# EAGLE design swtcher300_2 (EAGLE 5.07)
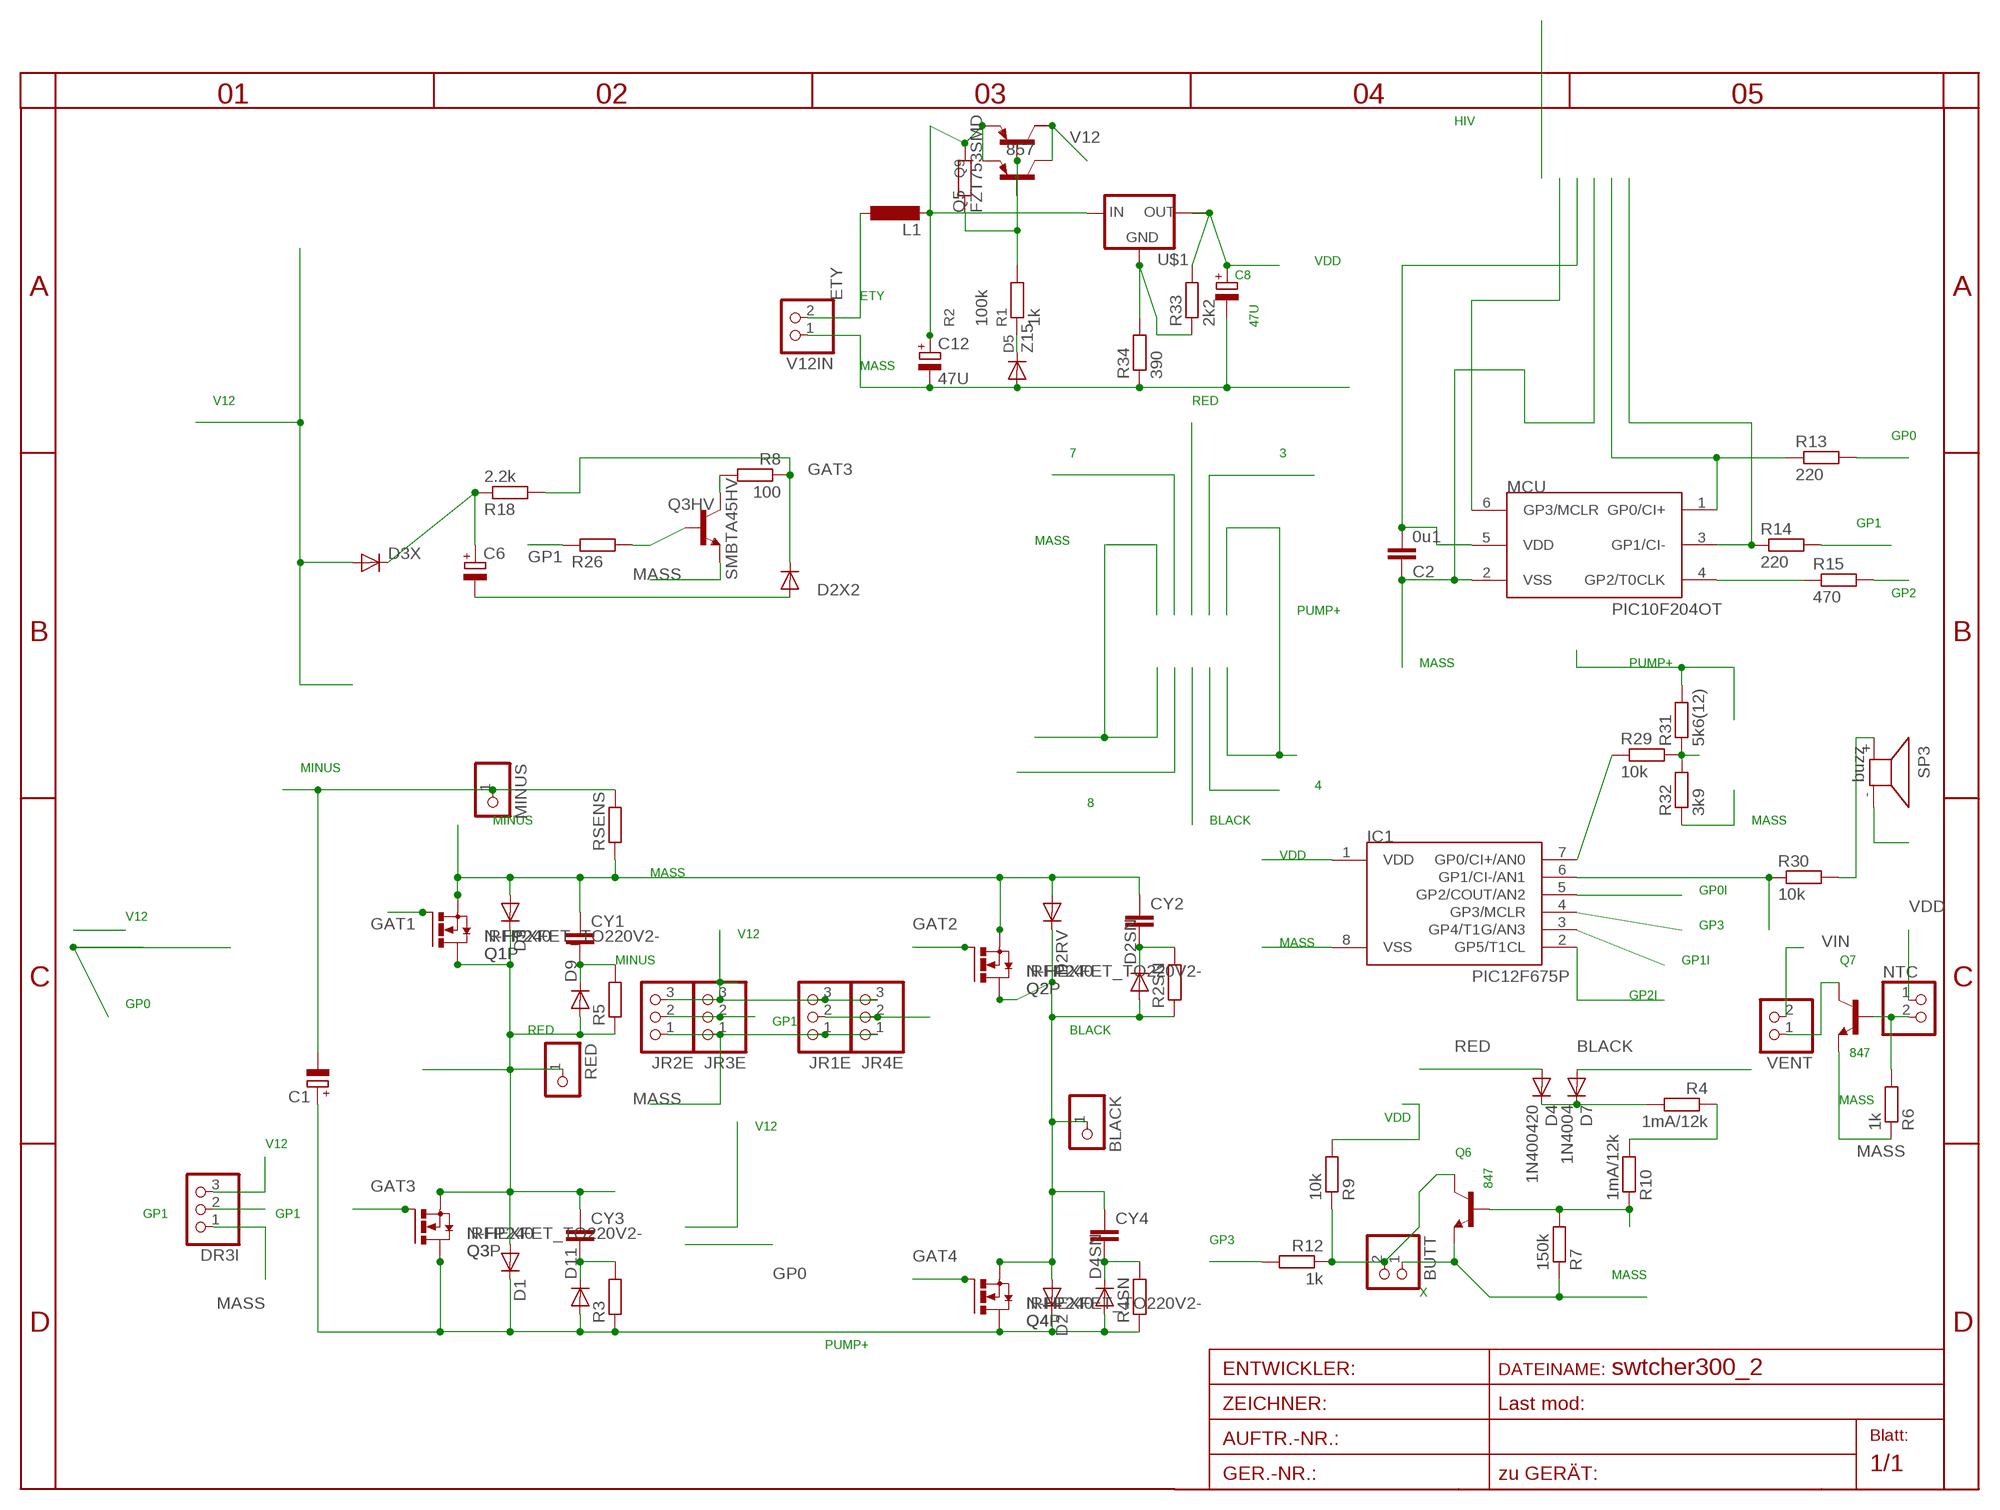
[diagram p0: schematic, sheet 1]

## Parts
BLACK  PINHD-1X14.5MM  [1X4MM5]
BUTT  PINHD-1X2STR  [1X02]
C1  CPOL-EUE5-13  [E5-13]
C2  0u1  C-EUC0805  [C0805]
C6  CPOL-EUC  [PANASONIC_C]
C8  47U  CPOL-EUD  [PANASONIC_D]
C12  47U  CPOL-EUSMCA  [SMC_A]
CY1  CXXC10B6  [XC10B6]
CY2  CXXC10B6  [XC10B6]
CY3  CXXC10B5  [XC10B5]
CY4  CXXC10B6  [XC10B6]
D1  DIODE-SMC  [SMC]
D2  DIODE-SMC  [SMC]
D2RV  DIODE-SMC  [SMC]
D2SN  DIODE-SOD61E  [SOD61E]
D2X2  DIODE-MINIMELF  [MINIMELF]
D3  DIODE-SMC  [SMC]
D3X  DIODE-SMA-DO214  [SMA-DO214AC]
D4  1N400420  [DO41-20]
D4SN  DIODE-SOD61E  [SOD61E]
D5  Z15  DIODE-MINIMELF  [MINIMELF]
D7  1N4004  [D-7.5]
D9  DIODE-SOD61E  [SOD61E]
D11  DIODE-SOD61E  [SOD61E]
DR3I  PINHD-1X3  [1X03]
IC1  PIC12F675P  [DIL8]
JR1E  PINHD-1X3  [1X03]
JR2E  PINHD-1X3  [1X03]
JR3E  PINHD-1X3  [1X03]
JR4E  PINHD-1X3  [1X03]
L1  L-EU0204/5  [0204/5]
MCU  PIC10F204OT  [SOT23-6]
MINUS  PINHD-1X14.5MM  [1X4MM5]
NTC  PINHD-1X2STR  [1X02]
Q1  IRFP240  [TO247BV]
Q1P  N-HEXFET_TO220V2-  [TO220BV2]
Q2  IRFP240  [TO247BV]
Q2P  N-HEXFET_TO220V2-  [TO220BV2]
Q3  IRFP240  [TO247BV]
Q3HV  SMBTA45HV  [SOT23HV]
Q3P  N-HEXFET_TO220V2-  [TO220BV2]
Q4  IRFP240  [TO247BV]
Q4P  N-HEXFET_TO220V2-  [TO220BV2]
Q5  FZT753SMD  [SOT223]
Q6  847  BC847ALT1SMD  [SOT23]
Q7  847  BC847ALT1SMD  [SOT23]
Q9  857  BC857ALT1SMD  [SOT23-BEC]
R1  1k  R-EU_R0805  [R0805]
R2  100k  R-EU_R0805  [R0805]
R2SN  R-EU_0617/22  [0617/22]
R3  R-EU_0617/17  [0617/17]
R4  1mA/12k  R-EU_R1210  [R1210]
R4SN  R-EU_0617/22  [0617/22]
R5  R-EU_0617/22  [0617/22]
R6  1k  R-EU_R0805  [R0805]
R7  150k  R-EU_R0805  [R0805]
R8  100  R-EU_R0805  [R0805]
R9  10k  R-EU_R0805  [R0805]
R10  1mA/12k  R-EU_R1210  [R1210]
R12  1k  R-EU_R0805  [R0805]
R13  220  R-EU_R0805  [R0805]
R14  220  R-EU_R0805  [R0805]
R15  470  R-EU_R0805  [R0805]
R18  2.2k  R-EU_R1206  [R1206]
R26  R-EU_R0805  [R0805]
R29  10k  R-EU_R0805  [R0805]
R30  10k  R-EU_R0805  [R0805]
R31  5k6(12)  R-EU_0207/30  [0207/30]
R32  3k9  R-EU_R0805  [R0805]
R33  2k2  R-EU_R0805  [R0805]
R34  390  R-EU_R0805  [R0805]
RED  PINHD-1X14.5MM  [1X4MM5]
RSENS  R-EU_CERAM35  [CERAM35]
SP3  buzz  KSS12017MM  [KSS1202]
U$1  AP1117  [SOT223]
V12IN  PINHD-1X2STR  [1X02]
VENT  PINHD-1X2STR  [1X02]

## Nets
BLACK: BLACK.1 CY4.1 D2.A D2RV.C D2SN.A D7.A Q2.D Q2P.D Q4.S Q4P.S R2SN.1
ETY: L1.1 V12IN.2
GAT1: Q1.G Q1P.G
GAT2: Q2.G Q2P.G
GAT3: D2X2.C Q3.G Q3P.G R8.1 R18.2
GAT4: Q4.G Q4P.G
GP0: JR1E.2 JR4E.2 R13.2
GP0I: IC1.5(GP2/COUT/AN2) MCU.1(GP0/CI+) R13.1
GP1: DR3I.2 JR2E.2 JR3E.2 R14.2 R26.1
GP1I: IC1.3(GP4/T1G/AN3) MCU.3(GP1/CI-) R14.1
GP2: R15.2
GP2I: IC1.2(GP5/T1CL) MCU.4(GP2/T0CLK) R15.1
GP3: IC1.4(GP3/MCLR) MCU.6(GP3/MCLR) R12.2
MASS: BUTT.1 C2.1 C8.- C12.- CY1.1 CY2.1 D2RV.A D3.A D5.A DR3I.1 IC1.8(VSS) JR1E.1 JR2E.1 JR3E.1 JR4E.1 MCU.2(VSS) Q1.S Q1P.S Q2.S Q2P.S Q3HV.2(E) Q6.2(E) Q7.2(E) R6.1 R7.1 R32.1 R34.1 RSENS.1 SP3.- V12IN.1
MINUS: C1.- MINUS.1 RSENS.2
N$1: D4.C D7.C R4.2
N$2: Q5.1(B) Q9.B R1.2 R2.1
N$3: D5.C R1.1
N$4: Q3HV.3(C) R8.2
N$5: Q6.1(B) R7.2 R10.1
N$7: R4.1 R10.2
N$9: NTC.2 Q7.1(B) R6.2
N$10: Q7.3(C) VENT.1
N$13: C6.+ D3X.K(C) R18.1
N$22: Q3HV.1(B) R26.2
N$24: R30.2 SP3.+
N$30: R33.1 R34.2 U$1.1(GND)
N$31: IC1.6(GP1/CI-/AN1) R30.1
N$34: R29.2 R31.1 R32.2
N$35: IC1.7(GP0/CI+/AN0) R29.1
PUMP+: C1.+ D1.C D2.C D4SN.A D11.A Q3.D Q3P.D Q4.D Q4P.D R3.1 R4SN.1 R31.2
RED: C6.- CY3.1 D1.A D2X2.A D3.C D4.A D9.A Q1.D Q1P.D Q3.S Q3P.S R5.1 RED.1
SNUB1: CY3.2 D11.C R3.2
SNUB2: CY4.2 D4SN.C R4SN.2
SNUB3: CY2.2 D2SN.C R2SN.2
SNUB4: CY1.2 D9.C R5.2
V12: D3X.A DR3I.3 JR1E.3 JR2E.3 JR3E.3 JR4E.3 Q5.2(C) Q9.C
VDD: C2.2 C8.+ IC1.1(VDD) MCU.5(VDD) NTC.1 R9.2 R33.2 U$1.2(OUT) U$1.4(TAB)
VIN: C12.+ L1.2 Q5.3(E) Q9.E R2.2 U$1.3(IN) VENT.2
X: BUTT.2 Q6.3(C) R9.1 R12.1
Unconnected: Q5.4(C/)

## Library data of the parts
BLACK MINUS RED = pinhead:PINHD-1X1: PIN HEADER
BUTT NTC V12IN VENT = pinhead:PINHD-1X2: PIN HEADER
C1 C6 = rcl:CPOL-EU: POLARIZED CAPACITOR, European symbol
C2 = rcl:C-EU: CAPACITOR, European symbol
C8 C12 = rcl-2:CPOL-EU: POLARIZED CAPACITOR, European symbol
CY1-CY4 = rcl:CX: X CAPACITOR
D1 D2 D2RV D2SN D2X2 D3 D3X D4SN D5 D9 D11 = diode:DIODE-: DIODE
D4 D7 = diode:1N4004: DIODE
DR3I JR1E JR2E JR3E JR4E = pinhead:PINHD-1X3: PIN HEADER
IC1 = microchip-5:PIC12F6*: uPC nW 1k Program Flash memory 2x Timer Comparator 10b A/D converter/ 4xIN
L1 = rcl:L-EU: INDUCTOR, European symbol
MCU = microchip-3:PIC10F2*: uPC nW 0,25/0,5k Program Flash memory Comparator
Q1-Q4 = transistor-power:IRFP240: HEXFET Power MosFet Source: http://www.irf.com/
Q1P Q2P Q3P Q4P = transistor-power:N-HEXFET_?-*: HEXFET® Power MOSFET
Q3HV = transistor-npn:SMBTA45
Q5 = transistor-pnp:FZT753SMD: PNP Transistor
Q6 Q7 = transistor-npn:BC847*: NPN Transistor
Q9 = transistor-pnp:BC857*: PNP Transistror
R1-R3 R13-R15 R29-R34 = rcl-2:R-EU_: RESISTOR, European symbol
R2SN R4 R4SN R5-R10 R12 R18 R26 RSENS = rcl:R-EU_: RESISTOR, European symbol
SP3 = buzzer:KSS1201: SPEAKER
U$1 = v-reg:AP1117

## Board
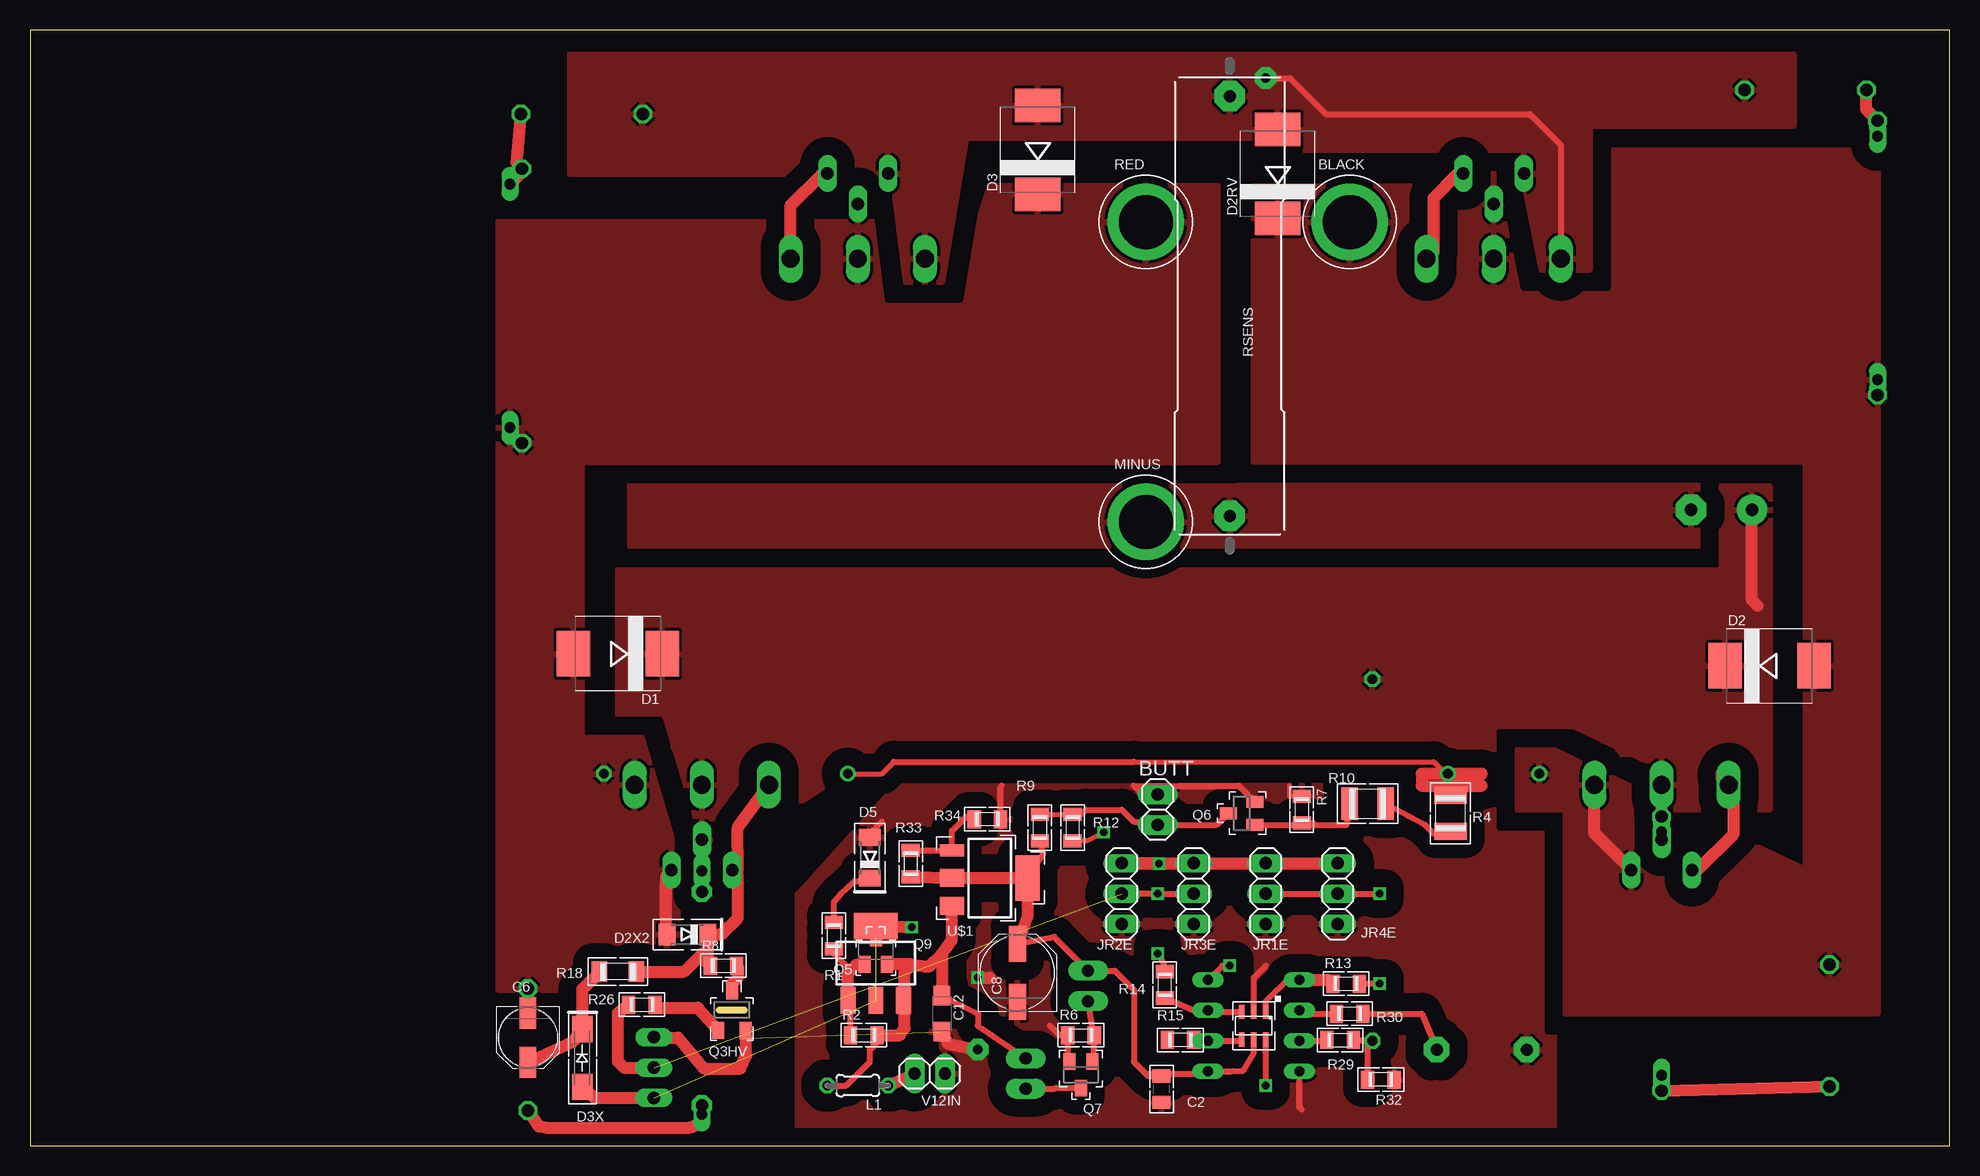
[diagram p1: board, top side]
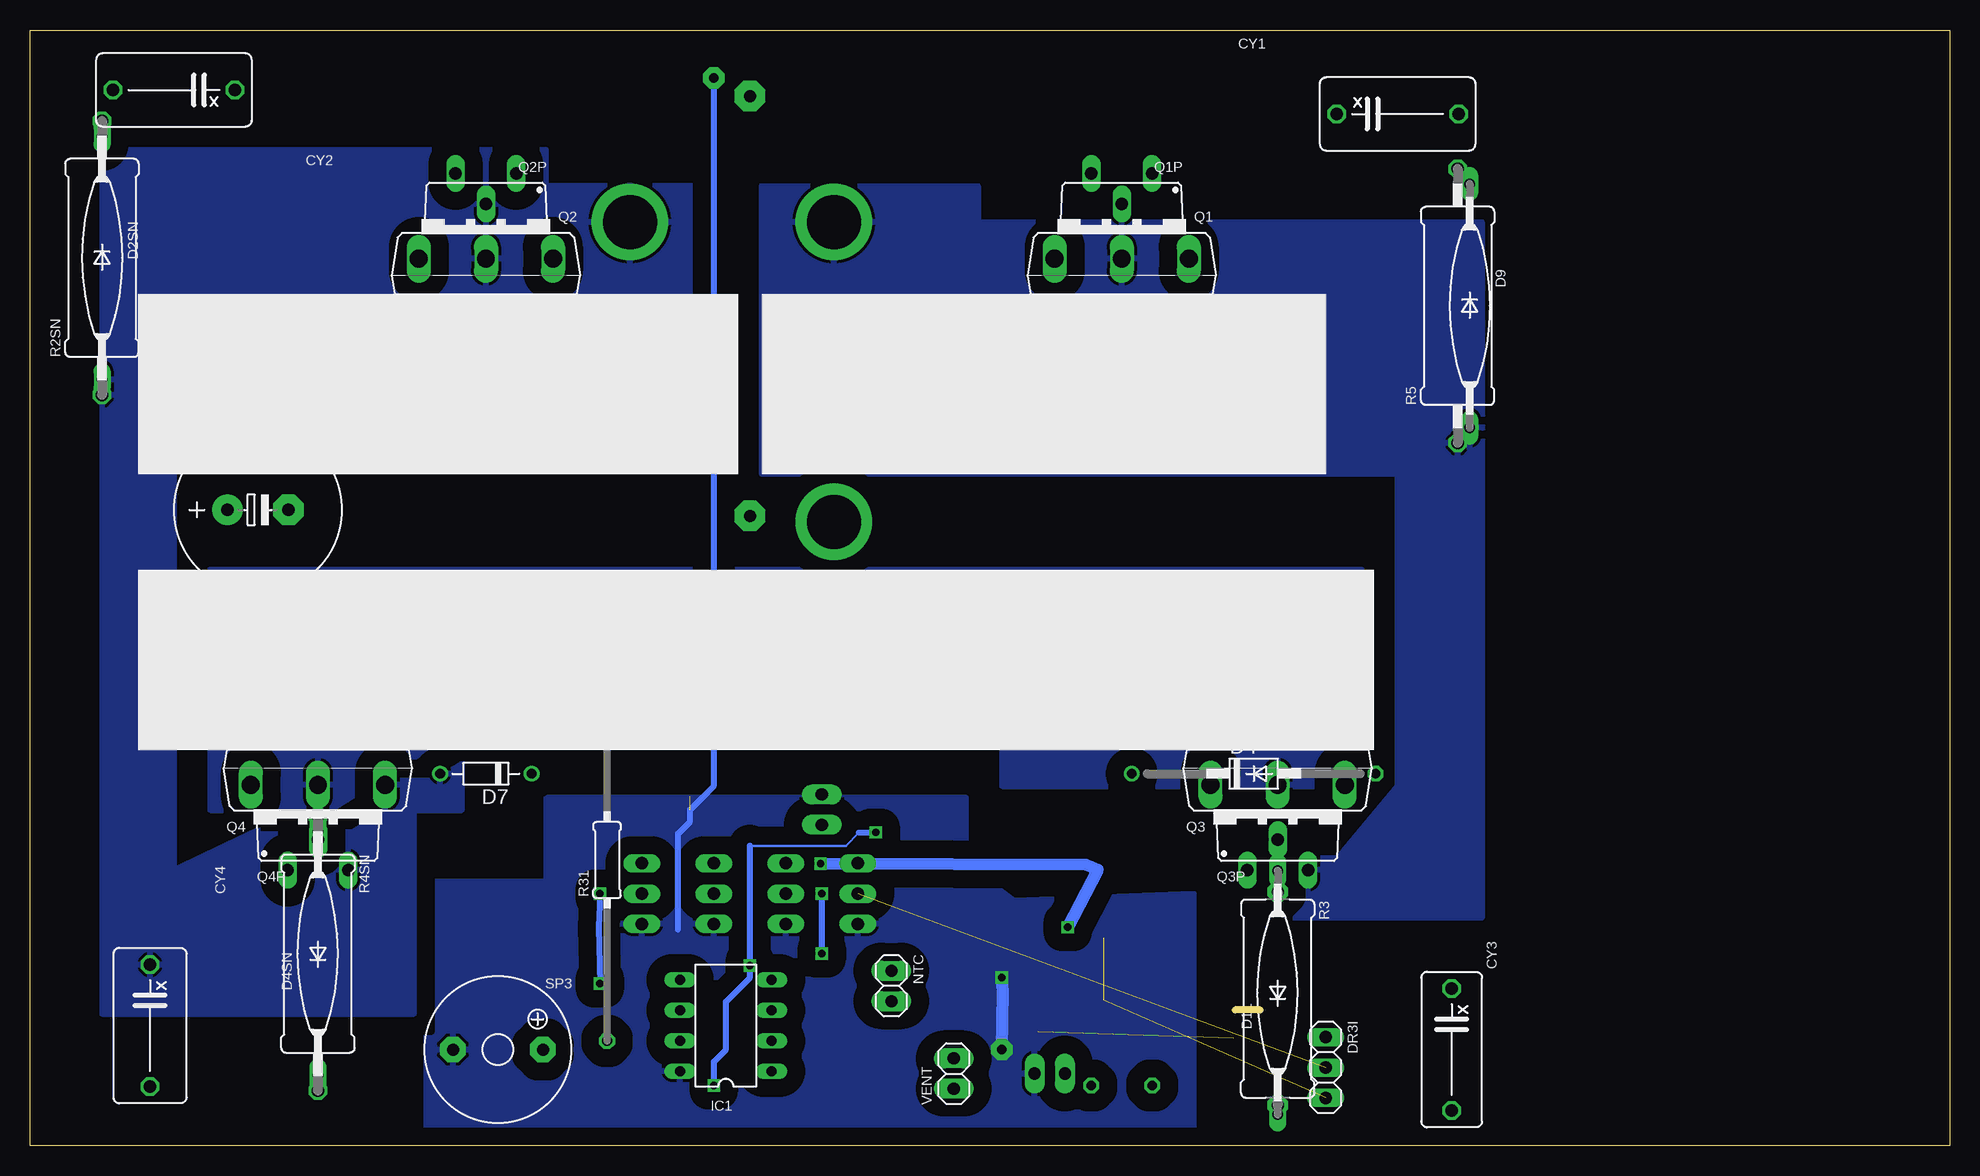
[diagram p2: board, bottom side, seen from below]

Size 160 x 93 mm. Coordinates in mm from the lower left corner, seen from the top.
Outline: 0,0 160,0 160,93 0,93 0,0
Copper layers (1*16): Top 0.035mm / dielectric 1.5mm / Bottom 0.035mm
Design rules "default *": minimum track width 10mil, minimum drill 20mil, track to track 8mil, track to pad 8mil, pad to pad 8mil, via to via 8mil, smd to smd 8mil, copper to edge 40mil, drill to drill 8mil, minimum pad ring 10mil, minimum via ring 8mil, stop-mask expansion 4mil, vias tented up to drill 0mil, thermal gap 10mil

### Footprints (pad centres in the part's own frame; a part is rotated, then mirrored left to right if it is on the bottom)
1X4MM5 = drill 4.5 pad 6.35 round: 1 0,0
1X02 = drill 1.016 pad 1.676 long: 1 -1.27,0; 2 1.27,0
E5-13 = drill 1.016 pad 2.54 round: + -2.54,0 | drill 1.016 pad 2.54 octagon: - 2.54,0
C0805 = smd 1.1 x 1.5: 1 -1.1,0; 2 1.1,0
PANASONIC_C = smd 2.6 x 1.4: + 2.05,0; - -2.05,0
PANASONIC_D = smd 3 x 1.4: + 2.4,0; - -2.4,0
SMC_A = smd 1.6 x 1.4: + -1.5,0; - 1.5,0
XC10B6 = drill 1.016 octagon: 1 -5.08,0; 2 5.08,0
XC10B5 = drill 1.016 octagon: 1 -5.08,0; 2 5.08,0
SMC = smd 2.8 x 3.8: A 3.7,0; C -3.7,0
SOD61E = drill 0.914 long: A 10.16,0; C -10.16,0
MINIMELF = smd 1.4 x 1.8: A 1.7,0; C -1.7,0
SMA-DO214AC = smd 2.2 x 1.7: A 2.4,0; K -2.4,0
DO41-20 = drill 0.8 octagon: A 10.16,0 | drill 0.8 round: C -10.16,0
D-7.5 = drill 0.8 round: A 3.81,0; C -3.81,0
1X03 = drill 1.016 long: 1 -2.54,0; 2 0,0; 3 2.54,0
DIL8 = drill 0.8 long: 1 -3.81,-3.81; 2 -1.27,-3.81; 3 1.27,-3.81; 4 3.81,-3.81; 5 3.81,3.81; 6 1.27,3.81; 7 -1.27,3.81; 8 -3.81,3.81
0204/5 = drill 0.813 octagon: 1 -2.54,0; 2 2.54,0
SOT23-6 = smd 0.45 x 1.2: 1 -1.016,-1.15; 2 0,-1.15; 3 1.016,-1.15; 4 1.016,1.15; 5 0,1.15; 6 -1.016,1.15
TO247BV = drill 1.499 long: D 0,-2.921; G -5.588,-2.921; S 5.588,-2.921
TO220BV2 = drill 1.016 long: D 0,0; G -2.54,-2.54; S 2.54,-2.54
SOT23HV = smd 1 x 1.4: 1 -1.15,-1.7; 2 1.15,-1.7; 3 0,1.6
SOT223 = smd 1.219 x 2.235: 1 -2.311,-3.099; 2 0,-3.099; 3 2.311,-3.099 | smd 3.6 x 2.2: 4 0,3.099
SOT23 = smd 1 x 1.4: 1 -0.95,-1.1; 2 0.95,-1.1; 3 0,1.1
SOT23-BEC = smd 1 x 1.4: B -0.95,-1.1; C 0,1.1; E 0.95,-1.1
R0805 = smd 1.1 x 1.5: 1 -1.1,0; 2 1.1,0
0617/22 = drill 1.016 octagon: 1 -11.43,0; 2 11.43,0
0617/17 = drill 1 pad 1.676 octagon: 1 -8.89,0; 2 8.89,0
R1210 = smd 1.4 x 2.7: 1 -1.5,0; 2 1.5,0
R1206 = smd 1.3 x 1.7: 1 -1.55,0; 2 1.55,0
0207/30 = drill 0.813 octagon: 1 -15.08,0; 2 15.08,0
CERAM35 = drill 1 pad 2.54 octagon: 1 -17.5,0; 2 17.5,0
KSS1202 = drill 1 pad 2.159 octagon: + 3.75,0; - -3.75,0
SOT223' = smd 1 x 2: 1 -2.3,-3.15 | smd 1.5 x 2: 2 0,-3.15; 3 2.3,-3.15 | smd 3.8 x 2: 4 0,3.15

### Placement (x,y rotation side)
BLACK  110,77 0 top
BUTT  94,28 270 top
C1  141,53 0 bottom
C2  94.32,4.7 90 top
C6  41.5,9 270 top
C8  82.3,14.4 90 top
C12  76,11 270 top
CY1  46,86 0 bottom
CY2  148,88 180 bottom
CY3  41.5,8 270 bottom
CY4  150,10 270 bottom
D1  49,41 180 top
D2  145,40 0 top
D2RV  104,81 90 top
D2SN  154,74 270 bottom
D2X2  54.8,17.6 180 top
D3  84,83 90 top
D3X  46.05,7.3 270 top
D4  58,31 0 bottom
D4SN  136,16 90 bottom
D5  70,24 90 top
D7  122,31 180 bottom
D9  40,70 270 bottom
D11  56,12.75 90 bottom
DR3I  52,6.5 270 bottom
IC1  102,10 90 bottom
JR1E  103,21 90 top
JR2E  91,21 90 top
JR3E  97,21 90 top
JR4E  109,21 90 top
L1  69,5 180 top
MCU  102,10 180 top
MINUS  93,52 0 top
NTC  88.2,13.3 270 bottom
Q1  69,71 180 bottom
Q1P  69,78.5 180 bottom
Q2  122,71 180 bottom
Q2P  122,78.5 180 bottom
Q3  56,33 0 bottom
Q3HV  58.5,11.3 0 top
Q3P  56,25.5 0 bottom
Q4  136,33 0 bottom
Q4P  136,25.5 0 bottom
Q5  70.5,15.2 0 top
Q6  101,27.7 90 top
Q7  87.6,5.9 180 top
Q9  70.5,16.2 0 top
R1  67,17.5 270 top
R2  69.5,9.2 0 top
R2SN  154,74 90 bottom
R3  56,12.25 270 bottom
R4  118.4,27.7 90 top
R4SN  136,16 270 bottom
R5  41,70 90 bottom
R6  87.6,9.2 0 top
R7  106,28 270 top
R8  57.8,15 0 top
R9  84.17,26.5 270 top
R10  111.5,28.5 0 top
R12  86.9,26.5 270 top
R13  109.7,13.5 0 top
R14  94.6,13.4 90 top
R15  95.9,8.8 180 top
R18  49,14.5 0 top
R26  51,11.75 0 top
R29  109.2,8.8 0 top
R30  110,11 0 top
R31  111.9,23.8 90 bottom
R32  112.6,5.5 180 top
R33  73.4,23.5 270 top
R34  79.8,27.2 180 top
RED  93,77 0 top
RSENS  100,70 270 top
SP3  121,8 0 bottom
U$1  AP1117  [SOT223']  80,22.3 270 top
V12IN  75,6 180 top
VENT  83,6 90 bottom

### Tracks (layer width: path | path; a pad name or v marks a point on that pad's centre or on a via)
BLACK
  Top 1: Q4.S 130.41,26.01 Q4P.S
  pour Top (isolate 1.5, rank 2): 102,80 117,80 117,83 154,83 154,11 128,11 128,28 124,28 124,33 127,33 148,23 148,57 102,57
  pour Bottom (isolate 1.5, rank 2): 102,80 117,80 117,83 154,83 154,11 128,11 128,28 124,28 124,33 127,33 148,23 148,57 102,57
ETY
  Top 1: L1.1 V12IN.2
GAT1
  Top 1: Q1.G 63.41,78.41 66,81 66.42,81 Q1P.G
GAT2
  Top 1: Q2P.G 119.04,81.04 117,79 117,74.51 Q2.G
GAT3
  Top 1: Q3.G 58.99,26.49 59,23 58.68,23 Q3P.G 59,22.5 59,19 57.6,17.6 D2X2.C 56.5,15.5 56.35,15.35 | R18.2 54.5,14.5 56,16 56,15.7 56.35,15.35 | 56.35,15.35 R8.1
GAT4
  Top 1: Q4P.G 138.96,22.96 142,26 142,30 141,31 141,30.67 Q4.G
GP0  (via drill 0.6)
  Top 0.5: JR1E.2 JR4E.2 v112.5,21 | v112.5,13.5 R13.2
  Bottom 0.5: v112.5,13.5 112.6,18.2 v112.5,21
GP0I
  Top 0.5: MCU.1 103.02,12.02 105,14 105.62,14 IC1.5
  Top 1: IC1.5 108.26,13.81 R13.1
GP1  (via drill 0.6)  (1 unrouted)
  Top 0.5: R14.2 94.5,15.2 v94,16 | JR2E.2 v94,21 JR3E.2
  Top 1: DR3I.2 49.5,6.5 49,7 49,11.05 R26.1
  Bottom 0.5: v94,16 v94,21
GP1I
  Top 0.5: R14.1 97.03,11.27 IC1.3 98.31,11.15 MCU.3
GP2I
  Top 0.5: MCU.4 100.86,8.73 IC1.2 98.12,8.8 R15.1
GP3  (via drill 0.6)
  Top 0.406: R12.2 88.1,25.4 v89.5,26.1
  Top 0.5: MCU.6 103.02,6.02 v103,5 | v100,15 99.38,15 IC1.4
  Bottom 0.2: 90.9,26.1 92,25 100,25
  Bottom 0.5: v103,5 103,7 102,8 102,12 100,14 v100,15 100,25 | 90.9,26.1 v89.5,26.1
MASS  (via drill 0.6, 0.8 pad 1.78)  (2 unrouted)
  Top 0.406: R7.1 105,29.1 105,30
  Top 0.5: MCU.2 102,14 103,15 | IC1.8 105.81,3.19 106,3 | 85,10 85.8,9.2 R6.1 86.5,7.15 Q7.2 | D5.A 69.7,25.7 71,27 | Q2.S 127.59,83.41 125,86 108,86 105,89 v103,89 | R34.1 80.9,29.9 81,30 | BUTT.1 92.73,29.27 92,30 100.75,30 Q6.2
  Top 1: DR3I.1 52,9 54,9 56.2,6.4 59.2,6.4 59.7,7.5 59.7,8.95 Q3HV.2 | C12.- 76.5,8.5 v79,8 | v79,14 80,14
  Bottom 0.5: v103,89 103,30 105,28 105,27 106,26 106,18
  Bottom 1: v79,8 78.9,12.8 v79,14
  pour Top (isolate 1.5): 45,91 147,91 147,85 130,85 130,73 126,73 124,83 105,83 104,84 78,84 76,72 73,72 72,80 70,81 45,81
  pour Top (isolate 1.5, rank 3): 73,31 127,31 127,30 127,25 127,1 64,1 64,21
  pour Bottom (isolate 1.5, rank 3): 82,29 117,29 117,22 127,22 127,1 63,1 63,21 78,20.4 82,23.4
MINUS
  pour Top (isolate 1.5, rank 5): 145,50 50,50 50,56 145,56
N$1
  Top 0.406: D4.C 71,31 72,32 | D7.C 118,31 117,32 92,32
  Top 0.5: 72,32 92,32 | D7.C 118.4,30.79
  Top 1: 118.4,30.79 120.79,30.79 121,31 116,31 116,30 119.15,30 | 119.15,30 121,30 | 119.15,30 R4.2
N$2
  Top 0.5: R2.1 68.4,11.89 Q5.1 | R1.2 67,16 68.4,14.6
  Top 1: Q9.B 68.9,15.1 68.4,14.6 68.2,14.4 68.2,12.11 Q5.1
N$3
  Top 0.5: R1.1 67,20.3 67.6,21 68.7,22 D5.C
N$4
  Top 1: Q3HV.3 58.5,13.5 59,14 59,14.9 R8.2
N$5
  Top 0.406: R7.2 107,26.9 107,26.75
  Top 0.5: 109.77,28 R10.1 109.75,26.75 107,26.75 Q6.1
N$7
  Top 0.5: R10.2 116.23,26.77 117,26 118.25,26 R4.1
N$9
  Top 0.5: NTC.2 R6.2 88.7,7.15 Q7.1
N$10
  Top 0.5: VENT.1 85.43,4.73 85.5,4.8 Q7.3
N$13
  Top 1: R18.1 47.5,14.5 46.05,13.05 D3X.K 45.3,8.7 C6.+
N$22
  Top 1: Q3HV.1 55.65,11.5 52.35,11.5 R26.2
N$24
  Top 0.5: SP3.+ 116,11 R30.2
N$30
  Top 0.5: R33.1 U$1.1 76.85,26.25 78,27.4 78.2,27.4 R34.2
N$31
  Top 0.5: R30.1 105.81,11 IC1.6
N$34
  Top 0.5: R29.2 110.38,8.72 R31.1 111.5,8.32 R32.2
N$35
  Top 0.5: IC1.7 108.03,8.73 R29.1
PUMP+
  Top 0.5: R3.1 D11.A
  Top 1: D11.A Q3P.D | R4SN.1 D4SN.A | D4SN.A Q4.D | D4SN.A Q4P.D | C1.+ 143.54,45.46 144,45
  pour Top (isolate 1.5, rank 4): 145,55 145,28 119,28 117,33 71,33 57,24 49,24 49,48 141,48 141,55
  pour Bottom (isolate 1.5): 145,48 145,28 135,28 119,38 79,38 79,30 49,30 49,48
RED
  Top 1: D2X2.A 53,18 53,22.4 Q3P.S | C6.- CY3.1
  pour Top (isolate 1.5, rank 3): 99,57 99,80 80,80 79,77 39,77 39,13 54,13 54,24 51,34 46,34 46,57
  pour Bottom (isolate 1.5, rank 2): 99,56 99,80 81,80 81,77 39,77 39,19 61,19 61,24 51,24 46,30 46,56
SNUB1
  Top 0.5: 56,2 D11.C R3.2
  Top 1: CY3.2 42.43,1.57 43,1.5 55,1.5 56,2
SNUB2
  Top 1: CY4.2 R4SN.2 D4SN.C
SNUB3
  Top 1: CY2.2 153.08,86.35 R2SN.2 D2SN.C
SNUB4
  Top 1: CY1.2 40.57,81.86 R5.2 41,81.16 D9.C
V12  (via drill 0.6)  (2 unrouted)
  Top 1: D3X.A 46.1,4.9 47,4 51.96,4 DR3I.3 | JR4E.3 JR1E.3 JR3E.3 JR2E.3 93.54,23.54 v94.1,23.5 | v73.5,18.2 71.5,18.3 Q9.C
  Bottom 1: v94.1,23.5 72,23.4 71,23 v73.5,18.2
VDD
  Top 0.5: R9.2 84.47,24.32 U$1.4 | C8.+ 85.37,17.4 NTC.1 90.43,14.57 92,13 92,7 93,6 | 93,6 98,6 IC1.1 100.23,6.19 101.13,6.23 102,7.7 MCU.5 | C2.2 93.2,5.8 93,6
  Top 1: R33.2 U$1.2 U$1.4 83.15,19.15 C8.+
VIN
  Top 0.5: VENT.2 79,10 79,11 C12.+ | L1.2 68,5 70,7 70,8 71,9 70.8,9 R2.2
  Top 1: U$1.3 76.85,17.15 76,16 | 76,16 C12.+ | R2.2 72.5,9.2 72.9,9.8 72.9,11.8 72.91,12.2 | 72.91,12.2 Q5.3 | 73.5,15.1 Q9.E | 73.5,15.1 74.9,14.9 76,16 | 72.91,12.2 72.91,14.51 73.5,15.1
X
  Top 0.406: R9.1 R12.1
  Top 0.5: R12.1 87.6,27.6 88,28 91,28 92,27 93.73,27 BUTT.2 98.93,26.73 Q6.3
